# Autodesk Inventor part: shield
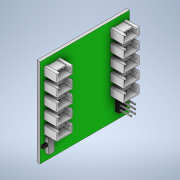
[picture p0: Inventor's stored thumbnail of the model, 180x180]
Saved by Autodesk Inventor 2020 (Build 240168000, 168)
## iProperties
Created: 2023-12
Part Number: shield
Material: Générique
Document SubType Name: Modeling
Designer: bruno
Density: 1 g/cm^3
Appearance: Par défaut
Author: bruno
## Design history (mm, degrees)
sketch "Esquisse1"
  geometry: L1 (0, 0)-(-56, 0); L2 (-56, 0)-(-56, -56.5); L3 (-56, -56.5)-(0, -56.5); L4 (0, -56.5)-(0, 0)
  constraints: 8 end point, 2 parallel, 1 horizontal, 1 perpendicular
  dimensions: "d0" = 56 distance of L3.end L2.end; "d1" = 56.5 distance of L2.end L1.end
extrude "Extrusion1" new body sketch "Esquisse1" distance "d2" = 1.8; taper "d3" = 0 deg
sketch "Esquisse2" dims "d40" = 42
  geometry: L1 (54.5, -4)-(44.5, -4); L2 (44.5, -4)-(44.5, -9); L3 (44.5, -9)-(54.5, -9); L4 (54.5, -9)-(54.5, -4); L5 (56.5, 0)-(0, 0) reference; L6 (56.5, -56)-(56.5, 0) reference; L7 (45.1, -4)-(52.7, -4); L8 (52.7, -4)-(52.7, -4.441); L9 (45.1, -8.4)-(53.9, -8.4); L10 (53.9, -8.4)-(53.9, -5.041); L11 (53.9, -5.041)-(45.1, -5.041); L12 (45.1, -5.041)-(45.1, -8.4); L13 (53.9, -5.041)-(53.3, -5.041); L14 (53.3, -5.041)-(53.3, -4.6); L15 (53.3, -4.6)-(53.9, -4.6); L16 (53.9, -4.6)-(53.9, -5.041); L17 (45.1, -5.041)-(45.7, -5.041); L18 (45.7, -5.041)-(45.7, -4.6); L19 (45.7, -4.6)-(45.1, -4.6); L20 (45.1, -4.6)-(45.1, -5.041); L21 (45.7, -5.041)-(45.1, -5.041); L22 (45.1, -5.041)-(45.1, -4.6); L23 (45.1, -4)-(45.7, -4); L24 (45.7, -4)-(45.7, -5.041); L25 (46.3, -4.441)-(46.3, -4); L26 (52.7, -4.441)-(46.3, -4.441); 4 further points
  constraints: 48 end point, 11 parallel, 7 perpendicular, 6 horizontal, 3 point on line
  dimensions: "d4" = 5 distance of L3.end L1.start; "d5" = 10 distance between parallel lines of L2 L4; "d6" = 4 distance between parallel lines of L5 L1; "d7" = 2 distance between parallel lines of L6 L4; "d8" = 0.6 distance between parallel lines of L3 L9; "d9" = 0.6 distance between parallel lines of L4 L10; "d10" = 0.6 distance between parallel lines of L12 L2; "d11" = 1.8 distance between parallel lines of L4 L8; "d13" = 0.6 distance between parallel lines of L15 L1; "d14" = 0.6 distance from line of L8 L13.end; "d16" = 7 distance between parallel lines of L24 L8; "d17" = 0.6 distance between parallel lines of L16 L14 (derived); "d18" = 0.6 distance between parallel lines of L18 L20; "d19" = 0.6 distance between parallel lines of L25 L24
extrude "Extrusion2" join sketch "Esquisse2" distance "d21" = 8; taper "d22" = 0 deg
sketch "Esquisse3"
  geometry: L1 (8, 0)-(8, -1.8) reference; L2 (0, 6.4)-(8, 6.4) reference; L3 (8, 0)-(5.544, 0); L4 (5.544, 0)-(5.544, 6.4); L5 (5.544, 6.4)-(8, 6.4); L6 (8, 6.4)-(8, 0); 2 further points
  constraints: 8 end point, 2 parallel, 1 horizontal, 1 perpendicular, 1 point on line
extrude "Extrusion3" cut sketch "Esquisse3" distance "d23" = 1; taper "d24" = 0 deg
sketch "Esquisse4"
  geometry: L1 (45.1, -8.4)-(45.1, -4.6) reference; L2 (45.1, -6.5)-(53.9, -6.5); L3 (53.9, -4.6)-(53.9, -8.4) reference; C1 r 0.3 at (46.032, -6.5); 1 further point
  constraints: 2 end point, 2 midpoint, 1 centre point, 1 point on line
  dimensions: "d25" = 0.6 diameter of C1
extrude "Extrusion4" join sketch "Esquisse4" distance "d26" = 5; taper "d27" = 0 deg; dims "d69" = 3, "d70" = 0
fillet "Congé1" dims "d28" = 0.3
pattern_linear "Réseau rectangulaire1" dims "d31" = 2
pattern_linear "Réseau rectangulaire3" dims "d40" = 42, "d43" = 8
pattern_linear "Réseau rectangulaire4" dims "d46" = 42, "d49" = 8
sketch "Esquisse5"
  geometry: L1 (47.368, -42.984)-(51.998, -42.984); L2 (51.998, -42.984)-(51.998, -50.921); L3 (51.998, -50.921)-(47.368, -50.921); L4 (47.368, -50.921)-(47.368, -42.984); 1 further point
  constraints: 8 end point, 2 parallel, 1 horizontal, 1 perpendicular
extrude "Extrusion5" join sketch "Esquisse5" distance "d50" = 2.5; taper "d51" = 0 deg
sketch "Esquisse6"
  geometry: C1 r 0.5 at (48.382, -44.242); 1 further point
  constraints: 1 centre point
  dimensions: "d52" = 1 diameter of C1
extrude "Extrusion6" join sketch "Esquisse6" distance "d53" = 7; taper "d54" = 0 deg
fillet "Congé2" dims "d55" = 0.3
pattern_linear "Réseau rectangulaire5" dims "d58" = 2.5, "d61" = 2.6
sketch "Esquisse7"
  geometry: L1 (3.167, -42.85)-(7.148, -42.85); L2 (7.148, -42.85)-(7.148, -51.932); L3 (7.148, -51.932)-(3.167, -51.932); L4 (3.167, -51.932)-(3.167, -42.85); 1 further point
  constraints: 8 end point, 2 parallel, 1 horizontal, 1 perpendicular
extrude "Extrusion7" join sketch "Esquisse7" distance "d62" = 1.9; taper "d63" = 0 deg
sketch "Esquisse8"
  geometry: L1 (0.342, 6.452)-(1.703, 6.452); L2 (1.703, 6.452)-(1.703, 4.658); L3 (1.703, 4.658)-(0.342, 4.658); L4 (0.342, 4.658)-(0.342, 6.452); 1 further point
  constraints: 8 end point, 2 parallel, 1 horizontal, 1 perpendicular
extrude "Extrusion8" join sketch "Esquisse8" distance "d64" = 3; taper "d65" = 0 deg
chamfer "Chanfrein1" distance "d66" = 0.5; stored, may be unused: second distance "d67" = 2, angle "d68" = 45 deg
node "Solide1"
other parameters: "d20" = 0.6
